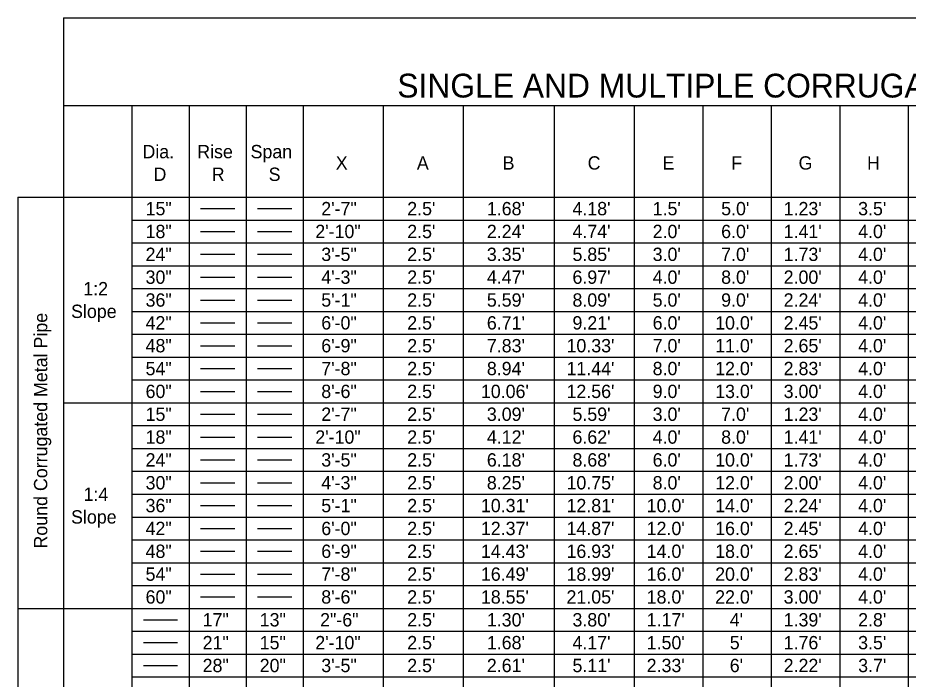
# Model space of a CAD drawing. Extents: x -1.3 to 14.4, y 0 to 7.8.
# Drawn here: x 1.7 to 6.38, y 4.278 to 7.752 of the extents above; entities that cross this region are included whole.
import ezdxf

# ---------------------------------------------------------------- set-up
doc = ezdxf.new("R2010")
doc.units = 0
doc.layers.add('Table', color=7, linetype='Continuous')

msp = doc.modelspace()

# ---------------------------------------------------------------- linework, layer by layer
at = {"layer": 'Table'}
for p, q in [((1.94, 7.7524), (13.46, 7.7524)), ((2.66, 6.75), (2.84, 6.75)), ((2.96, 6.75), (3.14, 6.75)), ((2.66, 6.63), (2.84, 6.63)), ((2.96, 6.63), (3.14, 6.63)), ((2.66, 6.51), (2.84, 6.51)), ((2.96, 6.51), (3.14, 6.51)), ((2.66, 6.39), (2.84, 6.39)), ((2.96, 6.39), (3.14, 6.39)), ((2.66, 6.27), (2.84, 6.27)), ((2.96, 6.27), (3.14, 6.27)), ((2.66, 6.15), (2.84, 6.15)), ((2.96, 6.15), (3.14, 6.15)), ((2.66, 6.03), (2.84, 6.03)), ((2.96, 6.03), (3.14, 6.03)), ((2.66, 5.91), (2.84, 5.91)), ((2.96, 5.91), (3.14, 5.91)), ((2.66, 5.79), (2.84, 5.79)), ((2.96, 5.79), (3.14, 5.79)), ((2.66, 5.67), (2.84, 5.67)), ((2.96, 5.67), (3.14, 5.67)), ((2.66, 5.55), (2.84, 5.55)), ((2.96, 5.55), (3.14, 5.55)), ((2.66, 5.43), (2.84, 5.43)), ((2.96, 5.43), (3.14, 5.43)), ((2.66, 5.31), (2.84, 5.31)), ((2.96, 5.31), (3.14, 5.31)), ((2.66, 5.19), (2.84, 5.19)), ((2.96, 5.19), (3.14, 5.19)), ((2.66, 5.07), (2.84, 5.07)), ((2.96, 5.07), (3.14, 5.07)), ((2.66, 4.95), (2.84, 4.95)), ((2.96, 4.95), (3.14, 4.95)), ((2.66, 4.83), (2.84, 4.83)), ((2.96, 4.83), (3.14, 4.83)), ((2.66, 4.71), (2.84, 4.71)), ((2.96, 4.71), (3.14, 4.71)), ((2.36, 4.59), (2.54, 4.59)), ((2.36, 4.47), (2.54, 4.47)), ((2.36, 4.35), (2.54, 4.35))]:
    msp.add_line(p, q, dxfattribs=at)
for points in [[(1.94, 7.7524), (1.94, 7.17), (1.94, 6.81), (1.94, 5.73), (1.94, 4.65), (1.94, 3.57), (1.94, 2.49)], [(13.46, 7.29), (11.78, 7.29), (10.1, 7.29), (8.42, 7.29), (8.06, 7.29), (6.38, 7.29), (6.02, 7.29), (5.66, 7.29), (5.3, 7.29), (4.94, 7.29), (4.52, 7.29), (4.04, 7.29), (3.62, 7.29), (3.2, 7.29), (2.9, 7.29), (2.6, 7.29), (2.3, 7.29), (1.94, 7.29)], [(2.3, 7.29), (2.3, 6.81), (2.3, 6.69), (2.3, 6.57), (2.3, 6.45), (2.3, 6.33), (2.3, 6.21), (2.3, 6.09), (2.3, 5.97), (2.3, 5.85), (2.3, 5.73), (2.3, 5.61), (2.3, 5.49), (2.3, 5.37), (2.3, 5.25), (2.3, 5.13), (2.3, 5.01), (2.3, 4.89), (2.3, 4.77), (2.3, 4.65), (2.3, 4.53), (2.3, 4.41), (2.3, 4.29), (2.3, 4.17)], [(2.6, 7.29), (2.6, 6.81), (2.6, 6.69), (2.6, 6.57), (2.6, 6.45), (2.6, 6.33), (2.6, 6.21), (2.6, 6.09), (2.6, 5.97), (2.6, 5.85), (2.6, 5.73), (2.6, 5.61), (2.6, 5.49), (2.6, 5.37), (2.6, 5.25), (2.6, 5.13), (2.6, 5.01), (2.6, 4.89), (2.6, 4.77), (2.6, 4.65), (2.6, 4.53), (2.6, 4.41), (2.6, 4.29), (2.6, 4.17)], [(2.9, 7.29), (2.9, 6.81), (2.9, 6.69), (2.9, 6.57), (2.9, 6.45), (2.9, 6.33), (2.9, 6.21), (2.9, 6.09), (2.9, 5.97), (2.9, 5.85), (2.9, 5.73), (2.9, 5.61), (2.9, 5.49), (2.9, 5.37), (2.9, 5.25), (2.9, 5.13), (2.9, 5.01), (2.9, 4.89), (2.9, 4.77), (2.9, 4.65), (2.9, 4.53), (2.9, 4.41), (2.9, 4.29), (2.9, 4.17)], [(3.2, 7.29), (3.2, 6.81), (3.2, 6.69), (3.2, 6.57), (3.2, 6.45), (3.2, 6.33), (3.2, 6.21), (3.2, 6.09), (3.2, 5.97), (3.2, 5.85), (3.2, 5.73), (3.2, 5.61), (3.2, 5.49), (3.2, 5.37), (3.2, 5.25), (3.2, 5.13), (3.2, 5.01), (3.2, 4.89), (3.2, 4.77), (3.2, 4.65), (3.2, 4.53), (3.2, 4.41), (3.2, 4.29), (3.2, 4.17)], [(3.62, 7.29), (3.62, 6.81), (3.62, 6.69), (3.62, 6.57), (3.62, 6.45), (3.62, 6.33), (3.62, 6.21), (3.62, 6.09), (3.62, 5.97), (3.62, 5.85), (3.62, 5.73), (3.62, 5.61), (3.62, 5.49), (3.62, 5.37), (3.62, 5.25), (3.62, 5.13), (3.62, 5.01), (3.62, 4.89), (3.62, 4.77), (3.62, 4.65), (3.62, 4.53), (3.62, 4.41), (3.62, 4.29), (3.62, 4.17)], [(4.04, 7.29), (4.04, 6.81), (4.04, 6.69), (4.04, 6.57), (4.04, 6.45), (4.04, 6.33), (4.04, 6.21), (4.04, 6.09), (4.04, 5.97), (4.04, 5.85), (4.04, 5.73), (4.04, 5.61), (4.04, 5.49), (4.04, 5.37), (4.04, 5.25), (4.04, 5.13), (4.04, 5.01), (4.04, 4.89), (4.04, 4.77), (4.04, 4.65), (4.04, 4.53), (4.04, 4.41), (4.04, 4.29), (4.04, 4.17)], [(4.52, 7.29), (4.52, 6.81), (4.52, 6.69), (4.52, 6.57), (4.52, 6.45), (4.52, 6.33), (4.52, 6.21), (4.52, 6.09), (4.52, 5.97), (4.52, 5.85), (4.52, 5.73), (4.52, 5.61), (4.52, 5.49), (4.52, 5.37), (4.52, 5.25), (4.52, 5.13), (4.52, 5.01), (4.52, 4.89), (4.52, 4.77), (4.52, 4.65), (4.52, 4.53), (4.52, 4.41), (4.52, 4.29), (4.52, 4.17)], [(4.94, 7.29), (4.94, 6.81), (4.94, 6.69), (4.94, 6.57), (4.94, 6.45), (4.94, 6.33), (4.94, 6.21), (4.94, 6.09), (4.94, 5.97), (4.94, 5.85), (4.94, 5.73), (4.94, 5.61), (4.94, 5.49), (4.94, 5.37), (4.94, 5.25), (4.94, 5.13), (4.94, 5.01), (4.94, 4.89), (4.94, 4.77), (4.94, 4.65), (4.94, 4.53), (4.94, 4.41), (4.94, 4.29), (4.94, 4.17)], [(5.3, 7.29), (5.3, 6.81), (5.3, 6.69), (5.3, 6.57), (5.3, 6.45), (5.3, 6.33), (5.3, 6.21), (5.3, 6.09), (5.3, 5.97), (5.3, 5.85), (5.3, 5.73), (5.3, 5.61), (5.3, 5.49), (5.3, 5.37), (5.3, 5.25), (5.3, 5.13), (5.3, 5.01), (5.3, 4.89), (5.3, 4.77), (5.3, 4.65), (5.3, 4.53), (5.3, 4.41), (5.3, 4.29), (5.3, 4.17)], [(5.66, 7.29), (5.66, 6.81), (5.66, 6.69), (5.66, 6.57), (5.66, 6.45), (5.66, 6.33), (5.66, 6.21), (5.66, 6.09), (5.66, 5.97), (5.66, 5.85), (5.66, 5.73), (5.66, 5.61), (5.66, 5.49), (5.66, 5.37), (5.66, 5.25), (5.66, 5.13), (5.66, 5.01), (5.66, 4.89), (5.66, 4.77), (5.66, 4.65), (5.66, 4.53), (5.66, 4.41), (5.66, 4.29), (5.66, 4.17)], [(6.02, 7.29), (6.02, 6.81), (6.02, 6.69), (6.02, 6.57), (6.02, 6.45), (6.02, 6.33), (6.02, 6.21), (6.02, 6.09), (6.02, 5.97), (6.02, 5.85), (6.02, 5.73), (6.02, 5.61), (6.02, 5.49), (6.02, 5.37), (6.02, 5.25), (6.02, 5.13), (6.02, 5.01), (6.02, 4.89), (6.02, 4.77), (6.02, 4.65), (6.02, 4.53), (6.02, 4.41), (6.02, 4.29), (6.02, 4.17)], [(6.38, 7.29), (6.38, 6.81), (6.38, 6.69), (6.38, 6.57), (6.38, 6.45), (6.38, 6.33), (6.38, 6.21), (6.38, 6.09), (6.38, 5.97), (6.38, 5.85), (6.38, 5.73), (6.38, 5.61), (6.38, 5.49), (6.38, 5.37), (6.38, 5.25), (6.38, 5.13), (6.38, 5.01), (6.38, 4.89), (6.38, 4.77), (6.38, 4.65), (6.38, 4.53), (6.38, 4.41), (6.38, 4.29), (6.38, 4.17)], [(1.7, 6.81), (1.94, 6.81), (2.3, 6.81), (2.6, 6.81), (2.9, 6.81), (3.2, 6.81), (3.62, 6.81), (4.04, 6.81), (4.52, 6.81), (4.94, 6.81), (5.3, 6.81), (5.66, 6.81), (6.02, 6.81), (6.38, 6.81), (6.8, 6.81)], [(1.7, 6.81), (1.7, 4.65), (1.7, 2.49)], [(2.3, 6.69), (2.6, 6.69), (2.9, 6.69), (3.2, 6.69), (3.62, 6.69), (4.04, 6.69), (4.52, 6.69), (4.94, 6.69), (5.3, 6.69), (5.66, 6.69), (6.02, 6.69), (6.38, 6.69), (6.8, 6.69)], [(2.3, 6.57), (2.6, 6.57), (2.9, 6.57), (3.2, 6.57), (3.62, 6.57), (4.04, 6.57), (4.52, 6.57), (4.94, 6.57), (5.3, 6.57), (5.66, 6.57), (6.02, 6.57), (6.38, 6.57), (6.8, 6.57)], [(2.3, 6.45), (2.6, 6.45), (2.9, 6.45), (3.2, 6.45), (3.62, 6.45), (4.04, 6.45), (4.52, 6.45), (4.94, 6.45), (5.3, 6.45), (5.66, 6.45), (6.02, 6.45), (6.38, 6.45), (6.8, 6.45)], [(2.3, 6.33), (2.6, 6.33), (2.9, 6.33), (3.2, 6.33), (3.62, 6.33), (4.04, 6.33), (4.52, 6.33), (4.94, 6.33), (5.3, 6.33), (5.66, 6.33), (6.02, 6.33), (6.38, 6.33), (6.8, 6.33)], [(2.3, 6.21), (2.6, 6.21), (2.9, 6.21), (3.2, 6.21), (3.62, 6.21), (4.04, 6.21), (4.52, 6.21), (4.94, 6.21), (5.3, 6.21), (5.66, 6.21), (6.02, 6.21), (6.38, 6.21), (6.8, 6.21)], [(2.3, 6.09), (2.6, 6.09), (2.9, 6.09), (3.2, 6.09), (3.62, 6.09), (4.04, 6.09), (4.52, 6.09), (4.94, 6.09), (5.3, 6.09), (5.66, 6.09), (6.02, 6.09), (6.38, 6.09), (6.8, 6.09)], [(2.3, 5.97), (2.6, 5.97), (2.9, 5.97), (3.2, 5.97), (3.62, 5.97), (4.04, 5.97), (4.52, 5.97), (4.94, 5.97), (5.3, 5.97), (5.66, 5.97), (6.02, 5.97), (6.38, 5.97), (6.8, 5.97)], [(2.3, 5.85), (2.6, 5.85), (2.9, 5.85), (3.2, 5.85), (3.62, 5.85), (4.04, 5.85), (4.52, 5.85), (4.94, 5.85), (5.3, 5.85), (5.66, 5.85), (6.02, 5.85), (6.38, 5.85), (6.8, 5.85)], [(1.94, 5.73), (2.3, 5.73), (2.6, 5.73), (2.9, 5.73), (3.2, 5.73), (3.62, 5.73), (4.04, 5.73), (4.52, 5.73), (4.94, 5.73), (5.3, 5.73), (5.66, 5.73), (6.02, 5.73), (6.38, 5.73), (6.8, 5.73)], [(2.3, 5.61), (2.6, 5.61), (2.9, 5.61), (3.2, 5.61), (3.62, 5.61), (4.04, 5.61), (4.52, 5.61), (4.94, 5.61), (5.3, 5.61), (5.66, 5.61), (6.02, 5.61), (6.38, 5.61), (6.8, 5.61)], [(2.3, 5.49), (2.6, 5.49), (2.9, 5.49), (3.2, 5.49), (3.62, 5.49), (4.04, 5.49), (4.52, 5.49), (4.94, 5.49), (5.3, 5.49), (5.66, 5.49), (6.02, 5.49), (6.38, 5.49), (6.8, 5.49)], [(2.3, 5.37), (2.6, 5.37), (2.9, 5.37), (3.2, 5.37), (3.62, 5.37), (4.04, 5.37), (4.52, 5.37), (4.94, 5.37), (5.3, 5.37), (5.66, 5.37), (6.02, 5.37), (6.38, 5.37), (6.8, 5.37)], [(2.3, 5.25), (2.6, 5.25), (2.9, 5.25), (3.2, 5.25), (3.62, 5.25), (4.04, 5.25), (4.52, 5.25), (4.94, 5.25), (5.3, 5.25), (5.66, 5.25), (6.02, 5.25), (6.38, 5.25), (6.8, 5.25)], [(2.3, 5.13), (2.6, 5.13), (2.9, 5.13), (3.2, 5.13), (3.62, 5.13), (4.04, 5.13), (4.52, 5.13), (4.94, 5.13), (5.3, 5.13), (5.66, 5.13), (6.02, 5.13), (6.38, 5.13), (6.8, 5.13)], [(2.3, 5.01), (2.6, 5.01), (2.9, 5.01), (3.2, 5.01), (3.62, 5.01), (4.04, 5.01), (4.52, 5.01), (4.94, 5.01), (5.3, 5.01), (5.66, 5.01), (6.02, 5.01), (6.38, 5.01), (6.8, 5.01)], [(2.3, 4.89), (2.6, 4.89), (2.9, 4.89), (3.2, 4.89), (3.62, 4.89), (4.04, 4.89), (4.52, 4.89), (4.94, 4.89), (5.3, 4.89), (5.66, 4.89), (6.02, 4.89), (6.38, 4.89), (6.8, 4.89)], [(2.3, 4.77), (2.6, 4.77), (2.9, 4.77), (3.2, 4.77), (3.62, 4.77), (4.04, 4.77), (4.52, 4.77), (4.94, 4.77), (5.3, 4.77), (5.66, 4.77), (6.02, 4.77), (6.38, 4.77), (6.8, 4.77)], [(1.7, 4.65), (1.94, 4.65), (2.3, 4.65), (2.6, 4.65), (2.9, 4.65), (3.2, 4.65), (3.62, 4.65), (4.04, 4.65), (4.52, 4.65), (4.94, 4.65), (5.3, 4.65), (5.66, 4.65), (6.02, 4.65), (6.38, 4.65), (6.8, 4.65)], [(2.3, 4.53), (2.6, 4.53), (2.9, 4.53), (3.2, 4.53), (3.62, 4.53), (4.04, 4.53), (4.52, 4.53), (4.94, 4.53), (5.3, 4.53), (5.66, 4.53), (6.02, 4.53), (6.38, 4.53), (6.8, 4.53)], [(2.3, 4.41), (2.6, 4.41), (2.9, 4.41), (3.2, 4.41), (3.62, 4.41), (4.04, 4.41), (4.52, 4.41), (4.94, 4.41), (5.3, 4.41), (5.66, 4.41), (6.02, 4.41), (6.38, 4.41), (6.8, 4.41)], [(2.3, 4.29), (2.6, 4.29), (2.9, 4.29), (3.2, 4.29), (3.62, 4.29), (4.04, 4.29), (4.52, 4.29), (4.94, 4.29), (5.3, 4.29), (5.66, 4.29), (6.02, 4.29), (6.38, 4.29), (6.8, 4.29)]]:
    msp.add_lwpolyline(points, dxfattribs=at)

# ---------------------------------------------------------------- texts
for s, height, p in [('SINGLE AND MULTIPLE CORRUGATED METAL PIPE DIMENSIONS AND QUANTITIES', 0.125, (3.6948, 7.3337)), ('Dia.', 0.07, (2.3552, 7.0145)), ('Rise', 0.07, (2.6431, 7.0145)), ('Span', 0.07, (2.9234, 7.0145)), ('X', 0.07, (3.3712, 6.955)), ('A', 0.07, (3.7975, 6.955)), ('B', 0.07, (4.2483, 6.955)), ('C', 0.07, (4.6952, 6.955)), ('E', 0.07, (5.0882, 6.955)), ('F', 0.07, (5.4503, 6.955)), ('G', 0.07, (5.8038, 6.955)), ('H', 0.07, (6.1637, 6.955)), ('D', 0.07, (2.4134, 6.8955)), ('R', 0.07, (2.7192, 6.8955)), ('S', 0.07, (3.0186, 6.8955)), ('1:2', 0.07, (2.0441, 6.2945)), ('Slope', 0.07, (1.98, 6.1755)), ('1:4', 0.07, (2.0455, 5.2145)), ('Slope', 0.07, (1.98, 5.0955))]:
    msp.add_text(s, height=height, dxfattribs=at).set_placement(p)
for s, rotation, p in [('2\'-7"', 0, (3.2951, 6.715)), ("2.5'", 0, (3.7469, 6.715)), ("1.68'", 0, (4.1654, 6.715)), ("4.18'", 0, (4.6154, 6.715)), ("5.0'", 0, (5.3969, 6.715)), ("1.23'", 0, (5.7254, 6.715)), ("3.5'", 0, (6.1169, 6.715)), ('15"', 0, (2.3715, 6.715)), ("1.5'", 0, (5.0369, 6.715)), ('18"', 0, (2.3715, 6.595)), ('2\'-10"', 0, (3.2637, 6.595)), ("2.5'", 0, (3.7469, 6.595)), ("2.24'", 0, (4.1654, 6.595)), ("4.74'", 0, (4.6154, 6.595)), ("2.0'", 0, (5.0369, 6.595)), ("6.0'", 0, (5.3969, 6.595)), ("1.41'", 0, (5.7254, 6.595)), ("4.0'", 0, (6.1169, 6.595)), ('24"', 0, (2.3715, 6.475)), ('3\'-5"', 0, (3.2951, 6.475)), ("2.5'", 0, (3.7469, 6.475)), ("3.35'", 0, (4.1654, 6.475)), ("5.85'", 0, (4.6154, 6.475)), ("3.0'", 0, (5.0369, 6.475)), ("7.0'", 0, (5.3969, 6.475)), ("1.73'", 0, (5.7254, 6.475)), ("4.0'", 0, (6.1169, 6.475)), ('30"', 0, (2.3715, 6.355)), ('4\'-3"', 0, (3.2951, 6.355)), ("2.5'", 0, (3.7469, 6.355)), ("4.47'", 0, (4.1654, 6.355)), ("6.97'", 0, (4.6154, 6.355)), ("4.0'", 0, (5.0369, 6.355)), ("8.0'", 0, (5.3969, 6.355)), ("2.00'", 0, (5.7254, 6.355)), ("4.0'", 0, (6.1169, 6.355)), ('36"', 0, (2.3715, 6.235)), ('5\'-1"', 0, (3.2951, 6.235)), ("2.5'", 0, (3.7469, 6.235)), ("5.59'", 0, (4.1654, 6.235)), ("8.09'", 0, (4.6154, 6.235)), ("5.0'", 0, (5.0369, 6.235)), ("9.0'", 0, (5.3969, 6.235)), ("2.24'", 0, (5.7254, 6.235)), ("4.0'", 0, (6.1169, 6.235)), ('Round Corrugated Metal Pipe', 90, (1.855, 4.9643)), ('42"', 0, (2.3715, 6.115)), ('6\'-0"', 0, (3.2951, 6.115)), ("2.5'", 0, (3.7469, 6.115)), ("6.71'", 0, (4.1654, 6.115)), ("9.21'", 0, (4.6154, 6.115)), ("6.0'", 0, (5.0369, 6.115)), ("10.0'", 0, (5.3654, 6.115)), ("2.45'", 0, (5.7254, 6.115)), ("4.0'", 0, (6.1169, 6.115)), ('48"', 0, (2.3715, 5.995)), ('6\'-9"', 0, (3.2951, 5.995)), ("2.5'", 0, (3.7469, 5.995)), ("7.83'", 0, (4.1654, 5.995)), ("10.33'", 0, (4.584, 5.995)), ("7.0'", 0, (5.0369, 5.995)), ("11.0'", 0, (5.3654, 5.995)), ("2.65'", 0, (5.7254, 5.995)), ("4.0'", 0, (6.1169, 5.995)), ('54"', 0, (2.3715, 5.875)), ('7\'-8"', 0, (3.2951, 5.875)), ("2.5'", 0, (3.7469, 5.875)), ("8.94'", 0, (4.1654, 5.875)), ("11.44'", 0, (4.584, 5.875)), ("8.0'", 0, (5.0369, 5.875)), ("12.0'", 0, (5.3654, 5.875)), ("2.83'", 0, (5.7254, 5.875)), ("4.0'", 0, (6.1169, 5.875)), ('60"', 0, (2.3715, 5.755)), ('8\'-6"', 0, (3.2951, 5.755)), ("2.5'", 0, (3.7469, 5.755)), ("10.06'", 0, (4.134, 5.755)), ("12.56'", 0, (4.584, 5.755)), ("9.0'", 0, (5.0369, 5.755)), ("13.0'", 0, (5.3654, 5.755)), ("3.00'", 0, (5.7254, 5.755)), ("4.0'", 0, (6.1169, 5.755)), ('15"', 0, (2.3715, 5.635)), ('2\'-7"', 0, (3.2951, 5.635)), ("2.5'", 0, (3.7469, 5.635)), ("3.09'", 0, (4.1654, 5.635)), ("5.59'", 0, (4.6154, 5.635)), ("3.0'", 0, (5.0369, 5.635)), ("7.0'", 0, (5.3969, 5.635)), ("1.23'", 0, (5.7254, 5.635)), ("4.0'", 0, (6.1169, 5.635)), ('18"', 0, (2.3715, 5.515)), ('2\'-10"', 0, (3.2637, 5.515)), ("2.5'", 0, (3.7469, 5.515)), ("4.12'", 0, (4.1654, 5.515)), ("6.62'", 0, (4.6154, 5.515)), ("4.0'", 0, (5.0369, 5.515)), ("8.0'", 0, (5.3969, 5.515)), ("1.41'", 0, (5.7254, 5.515)), ("4.0'", 0, (6.1169, 5.515)), ('24"', 0, (2.3715, 5.395)), ('3\'-5"', 0, (3.2951, 5.395)), ("2.5'", 0, (3.7469, 5.395)), ("6.18'", 0, (4.1654, 5.395)), ("8.68'", 0, (4.6154, 5.395)), ("6.0'", 0, (5.0369, 5.395)), ("10.0'", 0, (5.3654, 5.395)), ("1.73'", 0, (5.7254, 5.395)), ("4.0'", 0, (6.1169, 5.395)), ('30"', 0, (2.3715, 5.275)), ('4\'-3"', 0, (3.2951, 5.275)), ("2.5'", 0, (3.7469, 5.275)), ("8.25'", 0, (4.1654, 5.275)), ("10.75'", 0, (4.584, 5.275)), ("8.0'", 0, (5.0369, 5.275)), ("12.0'", 0, (5.3654, 5.275)), ("2.00'", 0, (5.7254, 5.275)), ("4.0'", 0, (6.1169, 5.275)), ('36"', 0, (2.3715, 5.155)), ('5\'-1"', 0, (3.2951, 5.155)), ("2.5'", 0, (3.7469, 5.155)), ("10.31'", 0, (4.134, 5.155)), ("12.81'", 0, (4.584, 5.155)), ("10.0'", 0, (5.0054, 5.155)), ("14.0'", 0, (5.3654, 5.155)), ("2.24'", 0, (5.7254, 5.155)), ("4.0'", 0, (6.1169, 5.155)), ('42"', 0, (2.3715, 5.035)), ('6\'-0"', 0, (3.2951, 5.035)), ("2.5'", 0, (3.7469, 5.035)), ("12.37'", 0, (4.134, 5.035)), ("14.87'", 0, (4.584, 5.035)), ("12.0'", 0, (5.0054, 5.035)), ("16.0'", 0, (5.3654, 5.035)), ("2.45'", 0, (5.7254, 5.035)), ("4.0'", 0, (6.1169, 5.035)), ('48"', 0, (2.3715, 4.915)), ('6\'-9"', 0, (3.2951, 4.915)), ("2.5'", 0, (3.7469, 4.915)), ("14.43'", 0, (4.134, 4.915)), ("16.93'", 0, (4.584, 4.915)), ("14.0'", 0, (5.0054, 4.915)), ("18.0'", 0, (5.3654, 4.915)), ("2.65'", 0, (5.7254, 4.915)), ("4.0'", 0, (6.1169, 4.915)), ('54"', 0, (2.3715, 4.795)), ('7\'-8"', 0, (3.2951, 4.795)), ("2.5'", 0, (3.7469, 4.795)), ("16.49'", 0, (4.134, 4.795)), ("18.99'", 0, (4.584, 4.795)), ("16.0'", 0, (5.0054, 4.795)), ("20.0'", 0, (5.3654, 4.795)), ("2.83'", 0, (5.7254, 4.795)), ("4.0'", 0, (6.1169, 4.795)), ('60"', 0, (2.3715, 4.675)), ('8\'-6"', 0, (3.2951, 4.675)), ("2.5'", 0, (3.7469, 4.675)), ("18.55'", 0, (4.134, 4.675)), ("21.05'", 0, (4.584, 4.675)), ("18.0'", 0, (5.0054, 4.675)), ("22.0'", 0, (5.3654, 4.675)), ("3.00'", 0, (5.7254, 4.675)), ("4.0'", 0, (6.1169, 4.675)), ('17"', 0, (2.6715, 4.555)), ('13"', 0, (2.9715, 4.555)), ('2"-6"', 0, (3.289, 4.555)), ("2.5'", 0, (3.7469, 4.555)), ("1.30'", 0, (4.1654, 4.555)), ("3.80'", 0, (4.6154, 4.555)), ("1.17'", 0, (5.0054, 4.555)), ("4'", 0, (5.4421, 4.555)), ("1.39'", 0, (5.7254, 4.555)), ("2.8'", 0, (6.1169, 4.555)), ('21"', 0, (2.6715, 4.435)), ('15"', 0, (2.9715, 4.435)), ('2\'-10"', 0, (3.2637, 4.435)), ("2.5'", 0, (3.7469, 4.435)), ("1.68'", 0, (4.1654, 4.435)), ("4.17'", 0, (4.6154, 4.435)), ("1.50'", 0, (5.0054, 4.435)), ("5'", 0, (5.4421, 4.435)), ("1.76'", 0, (5.7254, 4.435)), ("3.5'", 0, (6.1169, 4.435)), ('28"', 0, (2.6715, 4.315)), ('20"', 0, (2.9715, 4.315)), ('3\'-5"', 0, (3.2951, 4.315)), ("2.5'", 0, (3.7469, 4.315)), ("2.61'", 0, (4.1654, 4.315)), ("5.11'", 0, (4.6154, 4.315)), ("2.33'", 0, (5.0054, 4.315)), ("6'", 0, (5.4421, 4.315)), ("2.22'", 0, (5.7254, 4.315)), ("3.7'", 0, (6.1169, 4.315))]:
    msp.add_text(s, height=0.07, rotation=rotation, dxfattribs=at).set_placement(p)

doc.saveas('drawing.dxf')
